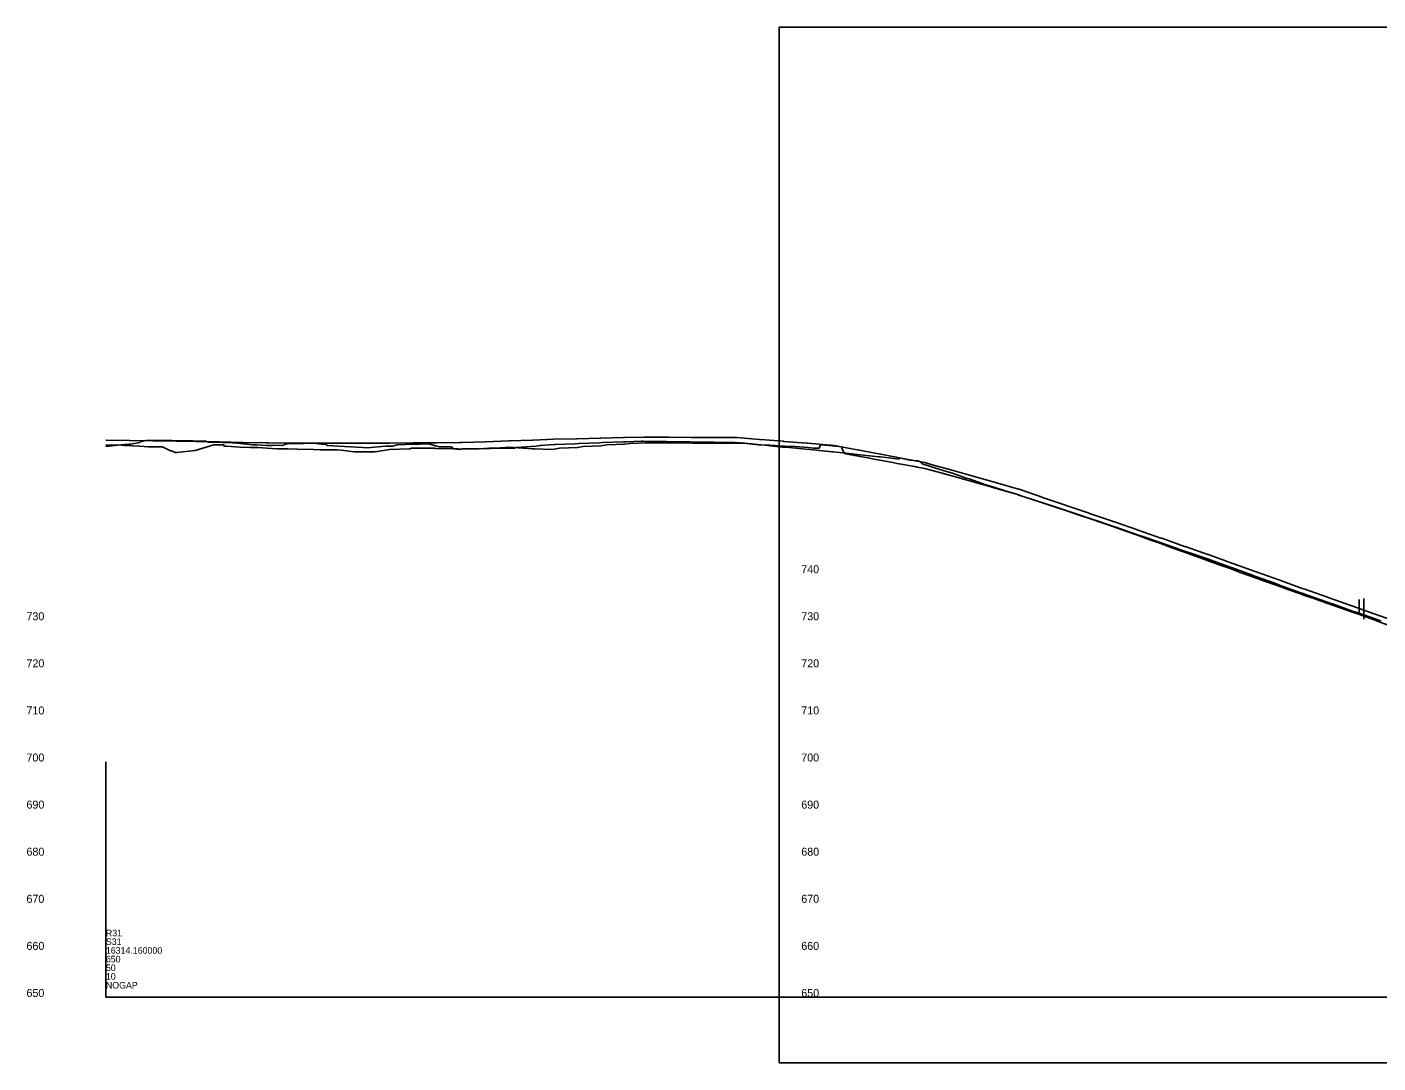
# Model space of a CAD drawing. Extents: x 1741783 to 1745041, y 1152835 to 1153935.
# Drawn here: x 1741783 to 1743218, y 1152835 to 1153935 of the extents above; entities that cross this region are included whole.
import ezdxf

# ---------------------------------------------------------------- set-up
doc = ezdxf.new("R2010")
doc.units = 0
for name, color, linetype in [('BR_EXIST_GROUND_LT', 7, 'Continuous'), ('BR_EXIST_GROUND_RT', 7, 'Continuous'), ('BR_USER NOTES', 7, 'Continuous'), ('GN_Clip', 7, 'Continuous'), ('RD_DDB_ElevTX', 7, 'Continuous'), ('RD_DDB_Profile_EX', 7, 'Continuous'), ('RD_GPK_Profile_Cell', 7, 'Continuous')]:
    doc.layers.add(name, color=color, linetype=linetype)

msp = doc.modelspace()

# ---------------------------------------------------------------- linework, layer by layer
at = {"layer": 'BR_EXIST_GROUND_LT'}
msp.add_lwpolyline([(1741866.9, 1153491.5), (1741880.6, 1153491.8), (1741886.8, 1153491), (1741894.9, 1153490.6), (1741902.7, 1153490.4), (1741912, 1153489.8), (1741927.2, 1153489.5), (1741935.4, 1153485.4), (1741936.7, 1153485.3), (1741940.5, 1153483.8), (1741942.3, 1153483.8), (1741961.8, 1153485.9), (1741981.4, 1153491.8), (1741992, 1153491.8), (1741992.3, 1153490.4), (1741995.1, 1153490.4), (1742009.6, 1153489.4), (1742020.1, 1153489.1), (1742028.4, 1153488.9), (1742042.7, 1153487.9), (1742048.7, 1153487.5), (1742059.7, 1153487.4), (1742070.4, 1153487), (1742087.4, 1153486.9), (1742094.5, 1153486.5), (1742112.7, 1153486.3), (1742116.9, 1153486.1), (1742130.6, 1153484.4), (1742141.3, 1153484.3), (1742142.1, 1153484.3), (1742152.8, 1153484.3), (1742168, 1153486.8), (1742189.1, 1153487.7), (1742190, 1153487.5), (1742191.1, 1153488.2), (1742192, 1153488.2), (1742209.5, 1153488.2), (1742216.4, 1153488.1), (1742216.9, 1153488), (1742240.6, 1153487.4), (1742241.9, 1153487.3), (1742244.2, 1153487.2), (1742268.2, 1153488), (1742269.1, 1153487.8), (1742269.9, 1153487.7), (1742291, 1153488.8), (1742294, 1153488.8), (1742296.7, 1153488.9), (1742297.4, 1153488.9), (1742299.8, 1153488.9), (1742320, 1153487.6), (1742322.3, 1153487.7), (1742339.8, 1153486.8), (1742342.8, 1153487.1), (1742348.6, 1153488.1), (1742367.8, 1153488.8), (1742373.6, 1153489.9), (1742392.8, 1153490.6), (1742398.5, 1153491.7), (1742417.8, 1153492.4), (1742423.1, 1153493.3), (1742440, 1153494), (1742446.9, 1153494), (1742464.9, 1153493.9), (1742474.1, 1153493.8), (1742489.9, 1153493.7), (1742502.4, 1153493.7), (1742514.8, 1153493.6), (1742532, 1153493.6), (1742537.9, 1153493.6), (1742544.9, 1153493.4), (1742562.9, 1153491.8), (1742571.8, 1153491.5), (1742587.8, 1153490.2), (1742599, 1153490), (1742612.8, 1153488.9), (1742618.3, 1153488.4), (1742624.4, 1153488.4), (1742625.9, 1153491.9), (1742626.6, 1153491.9), (1742627.4, 1153491.9), (1742631.1, 1153491.5), (1742645.1, 1153490.1), (1742647.4, 1153489.8), (1742647.8, 1153489.4), (1742648.5, 1153488.7), (1742650.9, 1153482.6), (1742658.1, 1153481.1), (1742675.9, 1153477.9), (1742682.6, 1153476.5), (1742700.9, 1153473.3), (1742707.1, 1153472), (1742725.9, 1153468.7), (1742728.5, 1153468.2), (1742736.4, 1153466.8), (1742754.9, 1153461.7), (1742761.3, 1153459.8), (1742779, 1153454.9), (1742786.3, 1153452.8), (1742803.2, 1153448.1), (1742811.3, 1153445.7), (1742827.5, 1153441.2), (1742836.3, 1153438.7), (1742836.8, 1153438.5), (1742851.7, 1153433.5), (1742861.8, 1153430.2), (1742875, 1153425.8), (1742886.7, 1153421.9), (1742898.3, 1153418), (1742911.7, 1153413.5), (1742921.7, 1153410.2), (1742936.7, 1153405.2), (1742937.3, 1153405), (1742946.3, 1153401.8), (1742962.3, 1153396.3), (1742970, 1153393.6), (1742987.3, 1153387.6), (1742993.5, 1153385.5), (1743012.3, 1153379), (1743016.9, 1153377.4), (1743037.6, 1153370.2), (1743038.3, 1153370), (1743060, 1153362.2), (1743063.2, 1153361), (1743084.6, 1153353.3), (1743088.1, 1153352), (1743109.2, 1153344.4), (1743113.1, 1153342.9), (1743133.8, 1153335.5), (1743138, 1153333.9), (1743138.4, 1153333.8), (1743140.8, 1153332.9), (1743145.1, 1153331.4), (1743165.7, 1153324.1), (1743170.4, 1153322.5), (1743190.7, 1153315.3), (1743195.6, 1153313.6), (1743215.6, 1153306.5), (1743220.9, 1153304.7)], dxfattribs=at)
at = {"layer": 'BR_EXIST_GROUND_RT'}
msp.add_lwpolyline([(1741867, 1153490.1), (1741882.9, 1153491.9), (1741891.8, 1153492.5), (1741893.4, 1153492.6), (1741902.8, 1153494.1), (1741903.6, 1153495.1), (1741909.4, 1153496.3), (1741931.4, 1153496.4), (1741933.3, 1153496.3), (1741936.8, 1153496.3), (1741956.3, 1153496.2), (1741959.1, 1153496.2), (1741968.5, 1153495.7), (1741973.2, 1153495.6), (1741975.7, 1153494.6), (1741980.7, 1153494.5), (1742001.1, 1153493.9), (1742002.1, 1153493.9), (1742006.4, 1153493.7), (1742022.7, 1153491.9), (1742027, 1153491.8), (1742037.7, 1153490.9), (1742039.8, 1153490.9), (1742043.7, 1153491.2), (1742055.9, 1153491.3), (1742056.5, 1153492.2), (1742059.8, 1153492.8), (1742062.4, 1153493.2), (1742076.6, 1153493.1), (1742085.7, 1153493.5), (1742087.8, 1153493.5), (1742095.7, 1153492.5), (1742100.8, 1153492.5), (1742101.6, 1153491.1), (1742120.3, 1153490), (1742126.7, 1153489.7), (1742139.6, 1153489), (1742144.3, 1153488.7), (1742163.8, 1153490.4), (1742169.1, 1153490.4), (1742171.3, 1153490.5), (1742176.2, 1153491.9), (1742184.7, 1153492), (1742188.9, 1153492.5), (1742200.6, 1153492.6), (1742209.4, 1153492.8), (1742220.8, 1153489.5), (1742232.7, 1153489.6), (1742235, 1153489.1), (1742235.7, 1153487.6), (1742242.6, 1153486.9), (1742245.4, 1153487.4), (1742263.3, 1153487.6), (1742270.3, 1153488), (1742273.5, 1153488.1), (1742294.2, 1153488.4), (1742295.9, 1153488.4), (1742300.7, 1153488.4), (1742302.5, 1153488.9), (1742323.8, 1153490.2), (1742327.9, 1153491), (1742343.3, 1153492), (1742344.3, 1153492.2), (1742365.3, 1153492.9), (1742369.2, 1153493.2), (1742390.9, 1153493.9), (1742394.2, 1153494.1), (1742416.5, 1153494.9), (1742419.2, 1153495.1), (1742435.7, 1153495.6), (1742437.3, 1153495.7), (1742459.8, 1153495.4), (1742462.3, 1153495.4), (1742484.2, 1153495.1), (1742487.4, 1153495), (1742508.4, 1153494.7), (1742512.4, 1153494.6), (1742530.8, 1153494.4), (1742535, 1153494.3), (1742540.9, 1153493.8), (1742560, 1153491.9), (1742566.6, 1153491.3), (1742585, 1153489.4), (1742592.3, 1153488.8), (1742610, 1153487), (1742618, 1153486.4), (1742635, 1153484.7), (1742637.8, 1153484.4), (1742639.3, 1153484.2), (1742659.3, 1153482.1), (1742664.3, 1153481.4), (1742687.7, 1153479.2), (1742689.4, 1153479), (1742709.3, 1153476.7), (1742709.6, 1153477.8), (1742720.5, 1153475.4), (1742729.1, 1153474.8), (1742730.5, 1153474.5), (1742733.6, 1153471.5), (1742757.2, 1153464.2), (1742758.4, 1153463.9), (1742767, 1153461.2), (1742780.4, 1153456.4), (1742783.5, 1153455.5), (1742801.4, 1153449.3), (1742808.8, 1153447.2), (1742822.7, 1153442.5), (1742834.1, 1153439.3), (1742835.8, 1153438.7), (1742836.4, 1153438.5), (1742849.8, 1153434.1), (1742861.4, 1153430.2), (1742875.2, 1153425.6), (1742886.3, 1153421.9), (1742900.5, 1153417.1), (1742911.3, 1153413.5), (1742925.9, 1153408.6), (1742936.2, 1153405.2), (1742950.9, 1153399.8), (1742961.1, 1153396.2), (1742975.5, 1153391), (1742986, 1153387.2), (1743000, 1153382.2), (1743011, 1153378.2), (1743024, 1153373.5), (1743035.7, 1153369.3), (1743047.9, 1153364.8), (1743060.7, 1153360.3), (1743072.5, 1153356), (1743085.6, 1153351.3), (1743097.2, 1153347.1), (1743110.6, 1153342.4), (1743121.9, 1153338.2), (1743135.5, 1153333.4), (1743136.7, 1153333), (1743138.5, 1153332.3), (1743148.6, 1153328.9), (1743163.5, 1153323.5), (1743172.6, 1153320.4), (1743188.5, 1153314.7), (1743196.9, 1153311.8), (1743213.5, 1153305.8), (1743216.9, 1153304.6), (1743233.6, 1153298.6)], dxfattribs=at)
at = {"layer": 'BR_USER NOTES'}
for p, q in [((1743197.7, 1153327.4), (1743197.7, 1153313.4)), ((1743202.7, 1153328.5), (1743202.7, 1153306.5)), ((1743197.7, 1153318), (1743202.7, 1153316.2))]:
    msp.add_line(p, q, dxfattribs=at)
at = {"layer": 'GN_Clip'}
for p, q in [((1742582, 1153935.4), (1744382, 1153935.4)), ((1742582, 1152835.4), (1742582, 1153935.4)), ((1744382, 1152835.4), (1742582, 1152835.4))]:
    msp.add_line(p, q, dxfattribs=at)
at = {"layer": 'RD_DDB_Profile_EX'}
msp.add_lwpolyline([(1741866.9, 1153496.9), (1741867.3, 1153496.9), (1741891.9, 1153496.5), (1741892.2, 1153496.5), (1741916.7, 1153496.1), (1741917.2, 1153496.1), (1741941.8, 1153495.7), (1741942.4, 1153495.7), (1741962.4, 1153495.3), (1741986.6, 1153494.8), (1741987.6, 1153494.8), (1742011.8, 1153494.3), (1742012.6, 1153494.3), (1742036.7, 1153493.8), (1742037.4, 1153493.8), (1742039.5, 1153493.8), (1742063.6, 1153493.7), (1742064.5, 1153493.7), (1742088.7, 1153493.6), (1742089.5, 1153493.6), (1742113.8, 1153493.6), (1742114.5, 1153493.6), (1742138.8, 1153493.5), (1742139.5, 1153493.5), (1742142.8, 1153493.5), (1742143.4, 1153493.5), (1742167.8, 1153493.7), (1742168.3, 1153493.7), (1742192.8, 1153493.8), (1742217.4, 1153494), (1742217.8, 1153494), (1742242.4, 1153494.2), (1742242.8, 1153494.2), (1742244.9, 1153494.2), (1742245.3, 1153494.2), (1742269.9, 1153495.1), (1742270.5, 1153495.1), (1742294.9, 1153496), (1742295.6, 1153496), (1742319.9, 1153496.9), (1742320.7, 1153496.9), (1742342.5, 1153497.7), (1742366.5, 1153498.2), (1742367.5, 1153498.3), (1742391.6, 1153498.8), (1742392.5, 1153498.8), (1742416.6, 1153499.4), (1742417.5, 1153499.4), (1742438.6, 1153499.9), (1742439.4, 1153499.9), (1742463.5, 1153499.8), (1742464.4, 1153499.8), (1742488.5, 1153499.7), (1742489.4, 1153499.7), (1742513.5, 1153499.6), (1742514.4, 1153499.6), (1742536.1, 1153499.5), (1742536.9, 1153499.5), (1742561.1, 1153497.5), (1742561.9, 1153497.5), (1742586.1, 1153495.5), (1742586.9, 1153495.4), (1742611.2, 1153493.5), (1742612.2, 1153493.4), (1742636.5, 1153491.4), (1742637, 1153491.3), (1742639.8, 1153491.1), (1742640.1, 1153491.1), (1742664.5, 1153486.5), (1742665, 1153486.4), (1742689.6, 1153481.7), (1742689.9, 1153481.7), (1742714.8, 1153477), (1742732.3, 1153473.7), (1742736.6, 1153472.9), (1742744.2, 1153470.7), (1742761.5, 1153465.8), (1742786.5, 1153458.8), (1742811.5, 1153451.7), (1742836.1, 1153444.7), (1742836.6, 1153444.6), (1742861.1, 1153436.2), (1742861.6, 1153436), (1742886, 1153427.7), (1742886.5, 1153427.5), (1742910.9, 1153419.2), (1742911.5, 1153419), (1742935.7, 1153410.7), (1742936.4, 1153410.4), (1742937.3, 1153410.1), (1742938, 1153409.9), (1742962.2, 1153401.4), (1742963, 1153401.2), (1742987.2, 1153392.7), (1742988, 1153392.5), (1743012.1, 1153384), (1743013, 1153383.7), (1743037.1, 1153375.3), (1743037.5, 1153375.2), (1743038.4, 1153374.8), (1743062.4, 1153366.2), (1743063.4, 1153365.9), (1743087.3, 1153357.3), (1743088.3, 1153356.9), (1743112.3, 1153348.3), (1743113.3, 1153348), (1743137.2, 1153339.3), (1743139.9, 1153338.4), (1743163.9, 1153329.9), (1743164.9, 1153329.6), (1743188.8, 1153321.1), (1743189.8, 1153320.8), (1743213.8, 1153312.3), (1743214.7, 1153312), (1743238.8, 1153303.5)], dxfattribs=at)
at = {"layer": 'RD_GPK_Profile_Cell'}
for q in [(1741866.9, 1153155.3), (1745041.2, 1152905.3), (1741866.9, 1152905.3)]:
    msp.add_line((1741866.9, 1152905.3), q, dxfattribs=at)

# ---------------------------------------------------------------- texts
at = {"layer": 'RD_DDB_ElevTX'}
for s, p in [('740', (1742605.3, 1153355.5)), ('730', (1741782.6, 1153305.5)), ('730', (1742605.3, 1153305.5)), ('720', (1741782.6, 1153255.5)), ('720', (1742605.3, 1153255.5)), ('710', (1741782.6, 1153205.5)), ('710', (1742605.3, 1153205.5)), ('700', (1741782.6, 1153155.5)), ('700', (1742605.3, 1153155.5)), ('690', (1741782.6, 1153105.5)), ('690', (1742605.3, 1153105.5)), ('680', (1741782.6, 1153055.5)), ('680', (1742605.3, 1153055.5)), ('670', (1741782.6, 1153005.5)), ('670', (1742605.3, 1153005.5)), ('660', (1741782.6, 1152955.5)), ('660', (1742605.3, 1152955.5)), ('650', (1741782.6, 1152905.5)), ('650', (1742605.3, 1152905.5))]:
    msp.add_text(s, height=8.5, dxfattribs=at).set_placement(p)
at = {"layer": 'RD_GPK_Profile_Cell'}
for s, p in [('S31', (1741866.9, 1152960.7)), ('R31', (1741866.9, 1152969.9)), ('16314.160000', (1741866.9, 1152951.4)), ('50', (1741866.9, 1152933)), ('650', (1741866.9, 1152942.2)), ('10', (1741866.9, 1152923.8)), ('NOGAP', (1741866.9, 1152914.5))]:
    msp.add_text(s, height=7, dxfattribs=at).set_placement(p)

doc.saveas('drawing.dxf')
